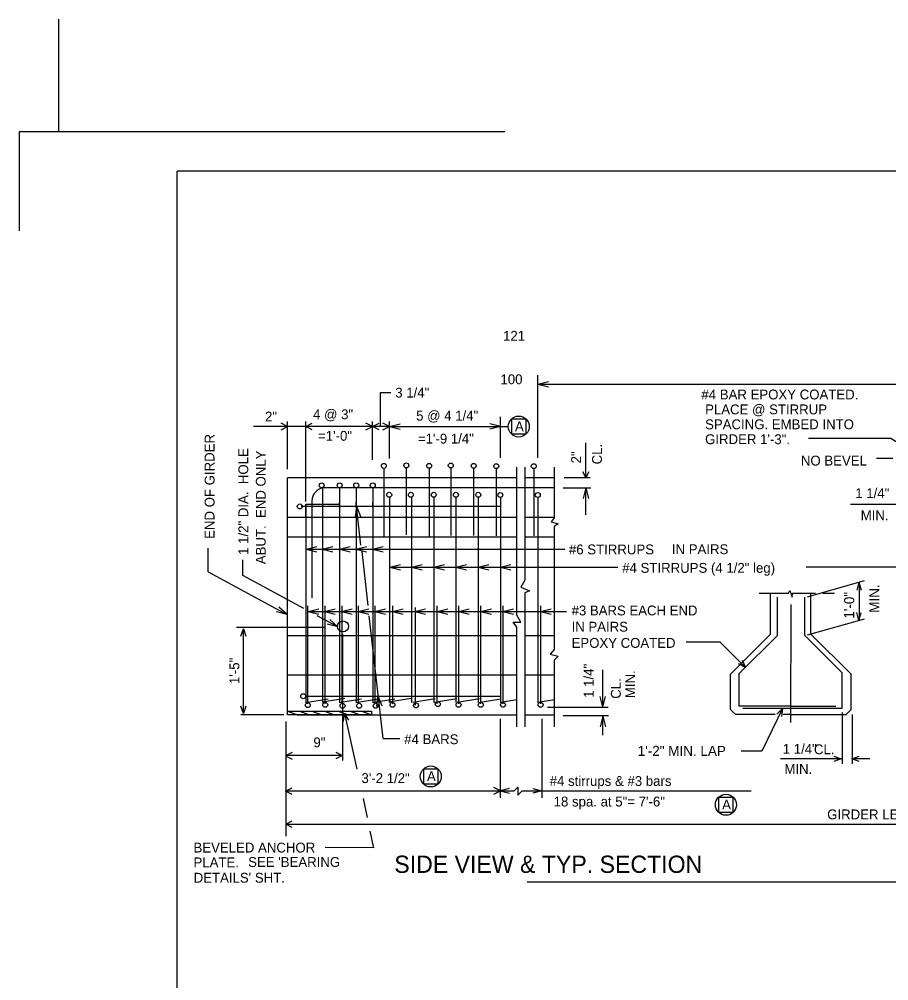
# Model space of a CAD drawing. Extents: x 1005.3 to 1101.9, y 1996.5 to 2073.3.
# Drawn here: x 1008.52 to 1037.89, y 2040.81 to 2073.29 of the extents above; entities that cross this region are included whole.
import ezdxf

# ---------------------------------------------------------------- set-up
doc = ezdxf.new("R2010")
doc.units = 0
for name, color, linetype in [('Level 1', 7, 'Continuous'), ('Level 2', 7, 'Continuous'), ('Level 5', 7, 'Continuous'), ('Level 6', 7, 'Continuous'), ('Level 60', 7, 'Continuous')]:
    doc.layers.add(name, color=color, linetype=linetype)

msp = doc.modelspace()

# ---------------------------------------------------------------- linework, layer by layer
at = {"layer": 'Level 1'}
for p, q in [((1024.919, 2069.489), (1008.518, 2069.489)), ((1008.518, 2069.489), (1008.518, 2066.149)), ((1013.852, 2012.158), (1013.852, 2068.156)), ((1097.517, 2068.156), (1013.852, 2068.156))]:
    msp.add_line(p, q, dxfattribs=at)
at = {"layer": 'Level 2'}
for p, q in [((1009.852, 2069.489), (1009.852, 2073.293)), ((1026.037, 2058.471), (1026.037, 2061.262)), ((1026.037, 2060.959), (1026.397, 2061.049)), ((1026.037, 2060.959), (1050.923, 2060.959)), ((1026.037, 2060.959), (1026.397, 2060.869)), ((1020.725, 2059.534), (1020.725, 2060.679)), ((1020.725, 2060.679), (1021.066, 2060.679)), ((1017.583, 2058.096), (1017.583, 2059.701)), ((1018.196, 2057.002), (1018.196, 2059.701)), ((1020.452, 2058.408), (1020.452, 2059.701)), ((1021.021, 2058.45), (1021.021, 2059.701)), ((1024.771, 2058.471), (1024.771, 2059.857)), ((1025.642, 2059.781), (1025.142, 2059.781)), ((1025.142, 2059.781), (1025.142, 2059.281)), ((1025.642, 2059.281), (1025.642, 2059.781)), ((1018.196, 2059.528), (1016.436, 2059.528)), ((1021.021, 2059.534), (1018.196, 2059.534)), ((1021.021, 2059.534), (1021.381, 2059.624)), ((1021.021, 2059.534), (1025.038, 2059.534)), ((1021.021, 2059.534), (1021.381, 2059.444)), ((1024.771, 2059.534), (1024.411, 2059.624)), ((1024.771, 2059.534), (1024.411, 2059.624)), ((1024.771, 2059.534), (1024.411, 2059.444)), ((1024.771, 2059.534), (1024.411, 2059.444)), ((1025.142, 2059.281), (1025.642, 2059.281)), ((1025.147, 2059.281), (1025.147, 2059.281)), ((1027.661, 2057.795), (1027.661, 2058.977)), ((1038.024, 2058.448), (1037.478, 2058.448)), ((1020.836, 2058.112), (1020.836, 2055.824)), ((1021.585, 2058.136), (1021.585, 2055.872)), ((1022.367, 2058.12), (1022.367, 2055.824)), ((1023.1, 2058.12), (1023.1, 2055.856)), ((1023.865, 2058.12), (1023.865, 2055.856)), ((1024.63, 2058.104), (1024.63, 2055.84)), ((1025.329, 2053.154), (1025.329, 2058.16)), ((1025.593, 2058.16), (1025.593, 2054.339)), ((1025.896, 2058.104), (1025.896, 2055.84)), ((1026.586, 2058.16), (1026.586, 2056.448)), ((1017.583, 2049.915), (1017.583, 2057.795)), ((1025.329, 2057.795), (1017.583, 2057.795)), ((1026.586, 2057.795), (1025.593, 2057.795)), ((1026.926, 2057.805), (1027.804, 2057.805)), ((1018.76, 2057.461), (1018.76, 2051.385)), ((1026.586, 2057.461), (1018.806, 2057.461)), ((1019.338, 2057.461), (1019.338, 2050.206)), ((1019.897, 2057.461), (1019.897, 2050.206)), ((1020.457, 2057.461), (1020.457, 2050.206)), ((1026.89, 2057.461), (1027.828, 2057.461)), ((1027.661, 2057.461), (1027.571, 2057.101)), ((1027.661, 2056.545), (1027.661, 2057.461)), ((1027.661, 2057.461), (1027.751, 2057.101)), ((1021.021, 2057.131), (1021.021, 2050.206)), ((1021.771, 2057.139), (1021.771, 2050.206)), ((1022.521, 2057.155), (1022.521, 2050.206)), ((1023.271, 2057.147), (1023.271, 2050.206)), ((1024.021, 2057.139), (1024.021, 2050.206)), ((1024.771, 2057.131), (1024.771, 2050.206)), ((1026.037, 2057.131), (1026.037, 2050.206)), ((1018.043, 2056.838), (1024.771, 2056.838)), ((1018.196, 2056.481), (1018.196, 2056.909)), ((1018.196, 2056.905), (1019.326, 2056.905)), ((1018.196, 2056.905), (1018.196, 2050.206)), ((1018.399, 2057.026), (1018.399, 2053.739)), ((1019.338, 2056.808), (1019.338, 2056.969)), ((1019.911, 2056.838), (1019.863, 2056.47)), ((1019.897, 2056.808), (1019.897, 2056.969)), ((1019.911, 2056.838), (1020.042, 2056.491)), ((1020.062, 2055.523), (1019.911, 2056.838)), ((1020.457, 2056.808), (1020.457, 2056.969)), ((1039.42, 2056.897), (1036.598, 2056.897)), ((1025.329, 2056.461), (1017.583, 2056.461)), ((1026.586, 2056.461), (1025.593, 2056.461)), ((1026.586, 2056.448), (1026.487, 2056.316)), ((1037.712, 2056.58), (1037.712, 2056.58)), ((1026.487, 2056.316), (1026.718, 2056.25)), ((1026.718, 2056.25), (1026.586, 2056.151)), ((1026.586, 2056.151), (1026.586, 2052.002)), ((1025.329, 2055.794), (1017.583, 2055.794)), ((1026.586, 2055.794), (1025.593, 2055.794)), ((1014.904, 2054.622), (1014.904, 2055.42)), ((1018.206, 2055.392), (1018.566, 2055.482)), ((1018.755, 2055.392), (1019.115, 2055.482)), ((1019.335, 2055.392), (1019.695, 2055.482)), ((1019.891, 2055.392), (1020.251, 2055.482)), ((1020.454, 2055.391), (1020.814, 2055.481)), ((1018.206, 2055.392), (1018.91, 2055.392)), ((1018.206, 2055.392), (1018.566, 2055.302)), ((1018.755, 2055.392), (1019.115, 2055.302)), ((1018.91, 2055.392), (1019.613, 2055.392)), ((1019.335, 2055.392), (1019.695, 2055.302)), ((1019.613, 2055.392), (1026.945, 2055.392)), ((1019.891, 2055.392), (1020.251, 2055.302)), ((1020.086, 2055.314), (1020.297, 2053.481)), ((1020.454, 2055.391), (1020.814, 2055.301)), ((1021.032, 2054.777), (1021.392, 2054.867)), ((1021.032, 2054.777), (1021.769, 2054.777)), ((1021.032, 2054.777), (1021.392, 2054.687)), ((1021.769, 2054.777), (1022.129, 2054.867)), ((1021.769, 2054.777), (1022.54, 2054.777)), ((1021.769, 2054.777), (1022.129, 2054.687)), ((1022.518, 2054.777), (1022.878, 2054.867)), ((1022.518, 2054.777), (1022.878, 2054.687)), ((1022.54, 2054.777), (1023.299, 2054.777)), ((1023.269, 2054.777), (1023.629, 2054.867)), ((1023.269, 2054.777), (1023.629, 2054.687)), ((1023.299, 2054.777), (1024.036, 2054.777)), ((1024.016, 2054.777), (1024.376, 2054.867)), ((1024.016, 2054.777), (1024.376, 2054.687)), ((1024.036, 2054.777), (1024.784, 2054.777)), ((1024.769, 2054.777), (1025.129, 2054.867)), ((1024.769, 2054.777), (1025.129, 2054.687)), ((1024.784, 2054.777), (1028.735, 2054.777)), ((1039.747, 2054.777), (1035.097, 2054.777)), ((1014.904, 2054.622), (1017.583, 2053.169)), ((1025.593, 2054.339), (1025.461, 2054.11)), ((1035.141, 2053.782), (1037.069, 2054.325)), ((1036.884, 2054.276), (1036.816, 2054.004)), ((1036.884, 2054.276), (1036.952, 2054.004)), ((1036.887, 2054.284), (1036.887, 2053)), ((1025.461, 2054.11), (1025.757, 2053.978)), ((1025.757, 2053.978), (1025.593, 2053.912)), ((1025.593, 2053.912), (1025.593, 2049.39)), ((1033.515, 2053.902), (1034.5, 2053.902)), ((1033.9, 2052.521), (1033.9, 2053.902)), ((1034.5, 2053.902), (1034.552, 2053.991)), ((1034.552, 2053.991), (1034.629, 2053.764)), ((1034.629, 2053.764), (1034.639, 2053.902)), ((1034.639, 2053.902), (1035.416, 2053.902)), ((1035.257, 2052.521), (1035.257, 2053.902)), ((1035.664, 2053.902), (1036.053, 2053.902)), ((1018.251, 2053.471), (1018.251, 2050.165)), ((1018.839, 2053.471), (1018.839, 2050.165)), ((1019.412, 2053.471), (1019.412, 2050.165)), ((1019.971, 2053.471), (1019.971, 2050.165)), ((1020.531, 2053.471), (1020.531, 2050.165)), ((1021.121, 2053.471), (1021.121, 2050.165)), ((1022.629, 2053.471), (1022.629, 2050.165)), ((1023.353, 2053.471), (1023.353, 2050.165)), ((1024.103, 2053.471), (1024.103, 2050.165)), ((1024.853, 2053.471), (1024.853, 2050.165)), ((1026.124, 2053.471), (1026.124, 2050.165)), ((1034.129, 2052.474), (1034.129, 2053.762)), ((1034.579, 2049.537), (1034.594, 2053.522)), ((1035.058, 2052.474), (1035.058, 2053.762)), ((1017.566, 2053.179), (1017.206, 2053.272)), ((1017.566, 2053.179), (1017.292, 2053.43)), ((1018.273, 2053.281), (1018.633, 2053.371)), ((1018.273, 2053.281), (1018.988, 2053.281)), ((1018.273, 2053.281), (1018.633, 2053.191)), ((1018.828, 2053.281), (1019.188, 2053.371)), ((1018.828, 2053.281), (1019.188, 2053.191)), ((1018.988, 2053.281), (1019.691, 2053.281)), ((1019.403, 2053.281), (1019.763, 2053.371)), ((1019.403, 2053.281), (1019.763, 2053.191)), ((1019.691, 2053.281), (1021.132, 2053.281)), ((1019.967, 2053.281), (1020.327, 2053.371)), ((1019.967, 2053.281), (1020.327, 2053.191)), ((1020.529, 2053.281), (1020.889, 2053.371)), ((1020.529, 2053.281), (1020.889, 2053.191)), ((1021.132, 2053.281), (1021.492, 2053.371)), ((1021.132, 2053.281), (1022.64, 2053.281)), ((1021.132, 2053.281), (1021.492, 2053.191)), ((1021.886, 2053.281), (1022.246, 2053.371)), ((1021.886, 2053.281), (1022.246, 2053.191)), ((1021.895, 2053.419), (1021.895, 2050.113)), ((1022.64, 2053.281), (1023, 2053.371)), ((1022.64, 2053.281), (1024.114, 2053.281)), ((1022.64, 2053.281), (1023, 2053.191)), ((1023.353, 2053.281), (1023.713, 2053.371)), ((1023.353, 2053.281), (1023.713, 2053.191)), ((1024.114, 2053.281), (1024.474, 2053.371)), ((1024.114, 2053.281), (1027.008, 2053.281)), ((1024.114, 2053.281), (1024.474, 2053.191)), ((1024.853, 2053.281), (1025.213, 2053.371)), ((1024.853, 2053.281), (1025.213, 2053.191)), ((1025.461, 2052.924), (1025.329, 2053.154)), ((1026.124, 2053.281), (1026.484, 2053.371)), ((1026.124, 2053.281), (1026.484, 2053.191)), ((1036.884, 2052.978), (1036.816, 2053.25)), ((1036.884, 2052.978), (1036.952, 2053.25)), ((1020.813, 2048.987), (1020.336, 2053.139)), ((1025.329, 2052.759), (1025.197, 2052.924)), ((1025.197, 2052.924), (1025.461, 2052.924)), ((1035.14, 2052.496), (1037.068, 2053.039)), ((1025.329, 2049.39), (1025.329, 2052.759)), ((1032.542, 2051.163), (1033.9, 2052.521)), ((1036.615, 2051.163), (1035.257, 2052.521)), ((1025.329, 2052.46), (1017.583, 2052.46)), ((1026.586, 2052.46), (1025.593, 2052.46)), ((1032.196, 2052.25), (1031.047, 2052.25)), ((1033.051, 2051.395), (1032.196, 2052.25)), ((1032.841, 2051.186), (1034.129, 2052.474)), ((1036.316, 2051.216), (1035.058, 2052.474)), ((1026.586, 2052.002), (1026.454, 2051.837)), ((1026.454, 2051.837), (1026.718, 2051.771)), ((1026.718, 2051.771), (1026.586, 2051.639)), ((1026.586, 2051.639), (1026.586, 2049.39)), ((1018.76, 2051.385), (1018.76, 2050.206)), ((1028.226, 2050.055), (1028.226, 2051.312)), ((1036.316, 2050.015), (1036.316, 2051.216)), ((1025.329, 2051.127), (1017.583, 2051.127)), ((1026.586, 2051.127), (1025.593, 2051.127)), ((1032.542, 2049.974), (1032.542, 2051.163)), ((1032.841, 2050.084), (1032.841, 2051.186)), ((1036.615, 2049.974), (1036.615, 2051.163)), ((1018.196, 2050.421), (1024.771, 2050.421)), ((1018.196, 2050.206), (1018.949, 2050.327)), ((1018.76, 2050.233), (1019.514, 2050.354)), ((1019.329, 2050.206), (1020.082, 2050.327)), ((1019.888, 2050.206), (1020.642, 2050.327)), ((1020.448, 2050.206), (1021.201, 2050.327)), ((1020.635, 2050.445), (1020.587, 2050.077)), ((1020.635, 2050.445), (1020.765, 2050.097)), ((1021.008, 2050.233), (1021.761, 2050.354)), ((1021.815, 2050.219), (1022.568, 2050.34)), ((1022.541, 2050.219), (1023.295, 2050.34)), ((1023.308, 2050.219), (1024.062, 2050.34)), ((1024.035, 2050.206), (1024.788, 2050.327)), ((1024.775, 2050.219), (1025.329, 2050.308)), ((1026.04, 2050.219), (1026.595, 2050.308)), ((1028.226, 2050.055), (1028.136, 2050.415)), ((1028.226, 2050.055), (1028.316, 2050.415)), ((1017.583, 2049.915), (1017.913, 2049.792)), ((1026.365, 2050.047), (1028.412, 2050.047)), ((1032.711, 2049.802), (1032.542, 2049.974)), ((1034.58, 2050.084), (1032.841, 2050.084)), ((1032.958, 2050.015), (1036.316, 2050.015)), ((1034.3, 2050.003), (1033.601, 2048.561)), ((1034.577, 2050.084), (1036.103, 2050.084)), ((1036.446, 2049.802), (1036.615, 2049.974)), ((1017.913, 2049.792), (1025.329, 2049.792)), ((1024.771, 2046.987), (1024.771, 2049.659)), ((1025.593, 2049.792), (1026.586, 2049.792)), ((1026.172, 2049.659), (1026.172, 2046.987)), ((1026.887, 2049.771), (1028.426, 2049.771)), ((1028.226, 2049.745), (1028.136, 2049.385)), ((1028.226, 2049.101), (1028.226, 2049.771)), ((1028.226, 2049.745), (1028.316, 2049.385)), ((1034.057, 2049.802), (1032.711, 2049.802)), ((1034.579, 2049.802), (1034.328, 2049.802)), ((1034.579, 2049.802), (1034.579, 2049.802)), ((1034.579, 2049.802), (1034.579, 2049.802)), ((1034.579, 2049.802), (1034.579, 2049.802)), ((1034.579, 2049.802), (1034.579, 2049.802)), ((1034.579, 2049.802), (1034.579, 2049.802)), ((1034.579, 2049.802), (1036.446, 2049.802)), ((1034.579, 2049.802), (1034.579, 2049.802)), ((1034.579, 2049.802), (1034.579, 2049.802)), ((1034.579, 2049.802), (1034.579, 2049.802)), ((1036.315, 2049.876), (1036.315, 2048.14)), ((1036.654, 2049.798), (1036.654, 2048.14)), ((1017.519, 2049.568), (1017.519, 2045.693)), ((1020.813, 2048.987), (1021.369, 2048.987)), ((1033.601, 2048.561), (1032.903, 2048.561)), ((1036.286, 2048.306), (1034.238, 2048.306)), ((1037.252, 2048.306), (1036.639, 2048.306)), ((1022.669, 2047.961), (1022.169, 2047.961)), ((1022.169, 2047.961), (1022.169, 2047.461)), ((1022.669, 2047.461), (1022.669, 2047.961)), ((1022.169, 2047.461), (1022.669, 2047.461)), ((1022.173, 2047.461), (1022.173, 2047.461)), ((1025.239, 2047.221), (1025.363, 2047.344)), ((1025.363, 2047.344), (1025.363, 2047.073)), ((1017.527, 2047.221), (1024.764, 2047.221)), ((1024.764, 2047.221), (1025.239, 2047.221)), ((1025.363, 2047.073), (1025.511, 2047.221)), ((1025.511, 2047.221), (1033.243, 2047.221)), ((1032.639, 2047.004), (1032.139, 2047.004)), ((1032.139, 2047.004), (1032.139, 2046.504)), ((1032.639, 2046.504), (1032.639, 2047.004)), ((1032.139, 2046.504), (1032.639, 2046.504)), ((1032.144, 2046.504), (1032.144, 2046.504)), ((1017.519, 2046.095), (1056.542, 2046.095)), ((1025.674, 2044.148), (1042.378, 2044.148))]:
    msp.add_line(p, q, dxfattribs=at)
for points in [[(1017.361, 2059.419), (1017.583, 2059.53), (1017.361, 2059.641)], [(1018.418, 2059.423), (1018.196, 2059.534), (1018.418, 2059.645)], [(1018.418, 2059.419), (1018.196, 2059.53), (1018.418, 2059.641)], [(1020.23, 2059.423), (1020.452, 2059.534), (1020.23, 2059.645)], [(1020.675, 2059.423), (1020.452, 2059.534), (1020.675, 2059.645)], [(1020.799, 2059.423), (1021.021, 2059.534), (1020.799, 2059.645)], [(1024.766, 2059.531), (1024.771, 2059.534), (1024.766, 2059.537)], [(1039.799, 2057.948), (1037.964, 2059.132), (1035.18, 2059.132)], [(1027.55, 2058.017), (1027.661, 2057.795), (1027.772, 2058.017)], [(1032.933, 2051.637), (1033.051, 2051.395), (1032.809, 2051.513)], [(1034.111, 2049.813), (1034.3, 2050.003), (1034.269, 2049.736)], [(1036.032, 2048.394), (1036.286, 2048.306), (1036.032, 2048.219)], [(1036.893, 2048.219), (1036.639, 2048.306), (1036.893, 2048.394)], [(1017.734, 2047.099), (1017.512, 2047.21), (1017.734, 2047.321)], [(1024.549, 2047.109), (1024.771, 2047.221), (1024.549, 2047.332)], [(1025.073, 2047.299), (1024.764, 2047.221), (1025.073, 2047.142)], [(1025.863, 2047.299), (1026.172, 2047.221), (1025.863, 2047.142)], [(1017.741, 2045.984), (1017.519, 2046.095), (1017.741, 2046.206)]]:
    msp.add_lwpolyline(points, dxfattribs=at)
for centre, radius in [((1025.392, 2059.531), 0.354), ((1020.834, 2058.202), 0.0833), ((1021.593, 2058.219), 0.0833), ((1022.364, 2058.205), 0.0833), ((1023.094, 2058.215), 0.0833), ((1023.867, 2058.203), 0.0833), ((1024.632, 2058.192), 0.0833), ((1025.898, 2058.192), 0.0833), ((1018.735, 2057.545), 0.0833), ((1019.342, 2057.545), 0.0833), ((1019.902, 2057.545), 0.0833), ((1020.461, 2057.545), 0.0833), ((1021.017, 2057.226), 0.0833), ((1021.746, 2057.226), 0.0833), ((1022.519, 2057.226), 0.0833), ((1023.269, 2057.226), 0.0833), ((1024.024, 2057.226), 0.0833), ((1024.768, 2057.218), 0.0833), ((1026.033, 2057.218), 0.0833), ((1017.994, 2056.832), 0.0833), ((1018.11, 2050.421), 0.0833), ((1022.656, 2050.153), 0.0833), ((1018.267, 2050.12), 0.0833), ((1018.855, 2050.131), 0.0833), ((1019.439, 2050.097), 0.0833), ((1019.998, 2050.097), 0.0833), ((1020.558, 2050.097), 0.0833), ((1021.126, 2050.131), 0.0833), ((1021.921, 2050.11), 0.0833), ((1023.358, 2050.131), 0.0833), ((1024.108, 2050.131), 0.0833), ((1024.858, 2050.131), 0.0833), ((1026.129, 2050.131), 0.0833), ((1022.419, 2047.711), 0.354), ((1032.389, 2046.754), 0.354)]:
    msp.add_circle(centre, radius, dxfattribs=at)
msp.add_arc((1018.865, 2056.998), 0.467, 96.657, 177.0425, dxfattribs=at)
at = {"layer": 'Level 5'}
for p, q in [((1016.076, 2054.497), (1016.076, 2055.029)), ((1018.136, 2053.381), (1016.076, 2054.497)), ((1019.28, 2052.76), (1018.587, 2053.136)), ((1019.28, 2052.76), (1018.921, 2052.852)), ((1019.28, 2052.76), (1019.007, 2053.011)), ((1018.819, 2052.744), (1015.861, 2052.744)), ((1016.09, 2049.832), (1016.09, 2052.699)), ((1019.437, 2052.522), (1019.437, 2048.253)), ((1017.454, 2049.787), (1015.998, 2049.787)), ((1019.437, 2048.419), (1017.527, 2048.419))]:
    msp.add_line(p, q, dxfattribs=at)
for points in [[(1016.002, 2052.445), (1016.09, 2052.699), (1016.177, 2052.445)], [(1016.177, 2050.086), (1016.09, 2049.832), (1016.002, 2050.086)], [(1017.734, 2048.52), (1017.512, 2048.409), (1017.734, 2048.298)], [(1019.215, 2048.531), (1019.437, 2048.419), (1019.215, 2048.308)]]:
    msp.add_lwpolyline(points, dxfattribs=at)
msp.add_circle((1019.455, 2052.778), 0.186, dxfattribs=at)
at = {"layer": 'Level 6'}
for p, q in [((1017.985, 2049.915), (1018.325, 2049.788)), ((1018.403, 2049.915), (1018.743, 2049.788)), ((1018.83, 2049.915), (1019.17, 2049.788)), ((1019.289, 2049.915), (1019.629, 2049.788)), ((1019.696, 2049.915), (1020.036, 2049.788)), ((1020.091, 2049.915), (1020.417, 2049.793)), ((1019.505, 2049.838), (1019.917, 2047.951)), ((1020.133, 2046.963), (1020.274, 2046.32)), ((1020.497, 2045.3), (1020.375, 2045.857)), ((1020.497, 2045.3), (1018.851, 2045.312))]:
    msp.add_line(p, q, dxfattribs=at)
msp.add_lwpolyline([(1017.583, 2049.915), (1020.417, 2049.915), (1020.417, 2049.788), (1017.583, 2049.788)], close=True, dxfattribs=at)
msp.add_lwpolyline([(1019.474, 2049.571), (1019.505, 2049.838), (1019.645, 2049.609)], dxfattribs=at)

# ---------------------------------------------------------------- texts
at = {"layer": 'Level 2'}
for s, height, p in [('3 1/4"', 0.3333, (1021.219, 2060.511)), ('#4 BAR EPOXY COATED. ', 0.33333, (1031.562, 2060.448)), (' PLACE @ STIRRUP', 0.33333, (1031.562, 2059.944)), ('2"', 0.3333, (1016.821, 2059.703)), ('4 @ 3" ', 0.3333, (1018.443, 2059.777)), ('5 @ 4 1/4"', 0.3333, (1021.925, 2059.733)), ('A', 0.333, (1025.264, 2059.371)), (' SPACING. EMBED INTO ', 0.33333, (1031.562, 2059.44)), ('=1\'-0"', 0.3333, (1018.612, 2059.052)), ('=1\'-9 1/4"', 0.3333, (1021.984, 2058.957)), (' GIRDER 1\'-3".', 0.33333, (1031.562, 2058.937)), ('NO BEVEL', 0.3333, (1034.922, 2058.214)), ('1 1/4"', 0.3333, (1036.758, 2057.114)), ('MIN.', 0.3333, (1036.942, 2056.368)), ('#6 STIRRUPS', 0.33333, (1027.087, 2055.213)), ('IN PAIRS', 0.3333, (1030.564, 2055.22)), ('#4 STIRRUPS (4 1/2" leg)', 0.33333, (1028.887, 2054.59)), ('#3 BARS EACH END', 0.33244, (1027.178, 2053.151)), ('IN PAIRS', 0.3324, (1027.178, 2052.603)), ('EPOXY COATED', 0.33244, (1027.178, 2052.055)), ('#4 BARS', 0.3333, (1021.522, 2048.801)), ('1\'-2" MIN. LAP', 0.34, (1029.41, 2048.404)), ('1 1/4"', 0.3333, (1034.31, 2048.474)), ('CL.', 0.3333, (1035.361, 2048.46)), ('MIN.', 0.3333, (1034.365, 2047.798)), ('3\'-2 1/2"', 0.3333, (1020.078, 2047.486)), ('A', 0.333, (1022.291, 2047.551)), ('#4 stirrups & #3 bars', 0.33333, (1026.437, 2047.39)), ('18 spa. at 5"= 7\'-6"', 0.33333, (1026.57, 2046.695)), ('A', 0.333, (1032.261, 2046.594)), ('GIRDER LENGTH =  "L"', 0.33333, (1035.81, 2046.261)), ('             SIDE VIEW & TYP. SECTION', 0.58333, (1018.37, 2044.452))]:
    msp.add_text(s, height=height, dxfattribs=at).set_placement(p)
for s, height, p in [('END OF GIRDER', 0.33333, (1015.115, 2055.738)), ('2"', 0.3333, (1027.495, 2058.286)), ('CL.', 0.3333, (1028.201, 2058.253)), ('MIN.', 0.34, (1037.573, 2053.241)), ('1\'-0"', 0.34, (1036.722, 2053.039)), ('1 1/4"', 0.3333, (1027.919, 2050.366)), ('MIN.', 0.3333, (1029.322, 2050.355)), ('CL.', 0.3333, (1028.837, 2050.334))]:
    msp.add_text(s, height=height, rotation=90, dxfattribs=at).set_placement(p)
at = {"layer": 'Level 5'}
for s, height, p in [('1 1/2" DIA.  HOLE', 0.33333, (1016.254, 2055.197)), ('ABUT.  END ONLY', 0.33333, (1016.844, 2054.881)), ('1\'-5"', 0.3333, (1015.953, 2050.833))]:
    msp.add_text(s, height=height, rotation=90, dxfattribs=at).set_placement(p)
msp.add_text('9"', height=0.3333, dxfattribs=at).set_placement((1018.455, 2048.695))
at = {"layer": 'Level 6'}
for s, height, p in [('BEVELED ANCHOR', 0.33333, (1014.405, 2045.14)), ('PLATE.', 0.3333, (1014.405, 2044.64)), ("SEE 'BEARING", 0.33333, (1016.251, 2044.653)), ("DETAILS' SHT.", 0.33333, (1014.411, 2044.121))]:
    msp.add_text(s, height=height, dxfattribs=at).set_placement(p)
at = {"layer": 'Level 60'}
for s, p in [('121', (1024.861, 2062.43)), ('100', (1024.774, 2060.96))]:
    msp.add_text(s, height=0.3333, dxfattribs=at).set_placement(p)

doc.saveas('drawing.dxf')
